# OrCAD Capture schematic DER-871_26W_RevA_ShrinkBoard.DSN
size A3; title: DER-871 26W; rev: A; note: NA
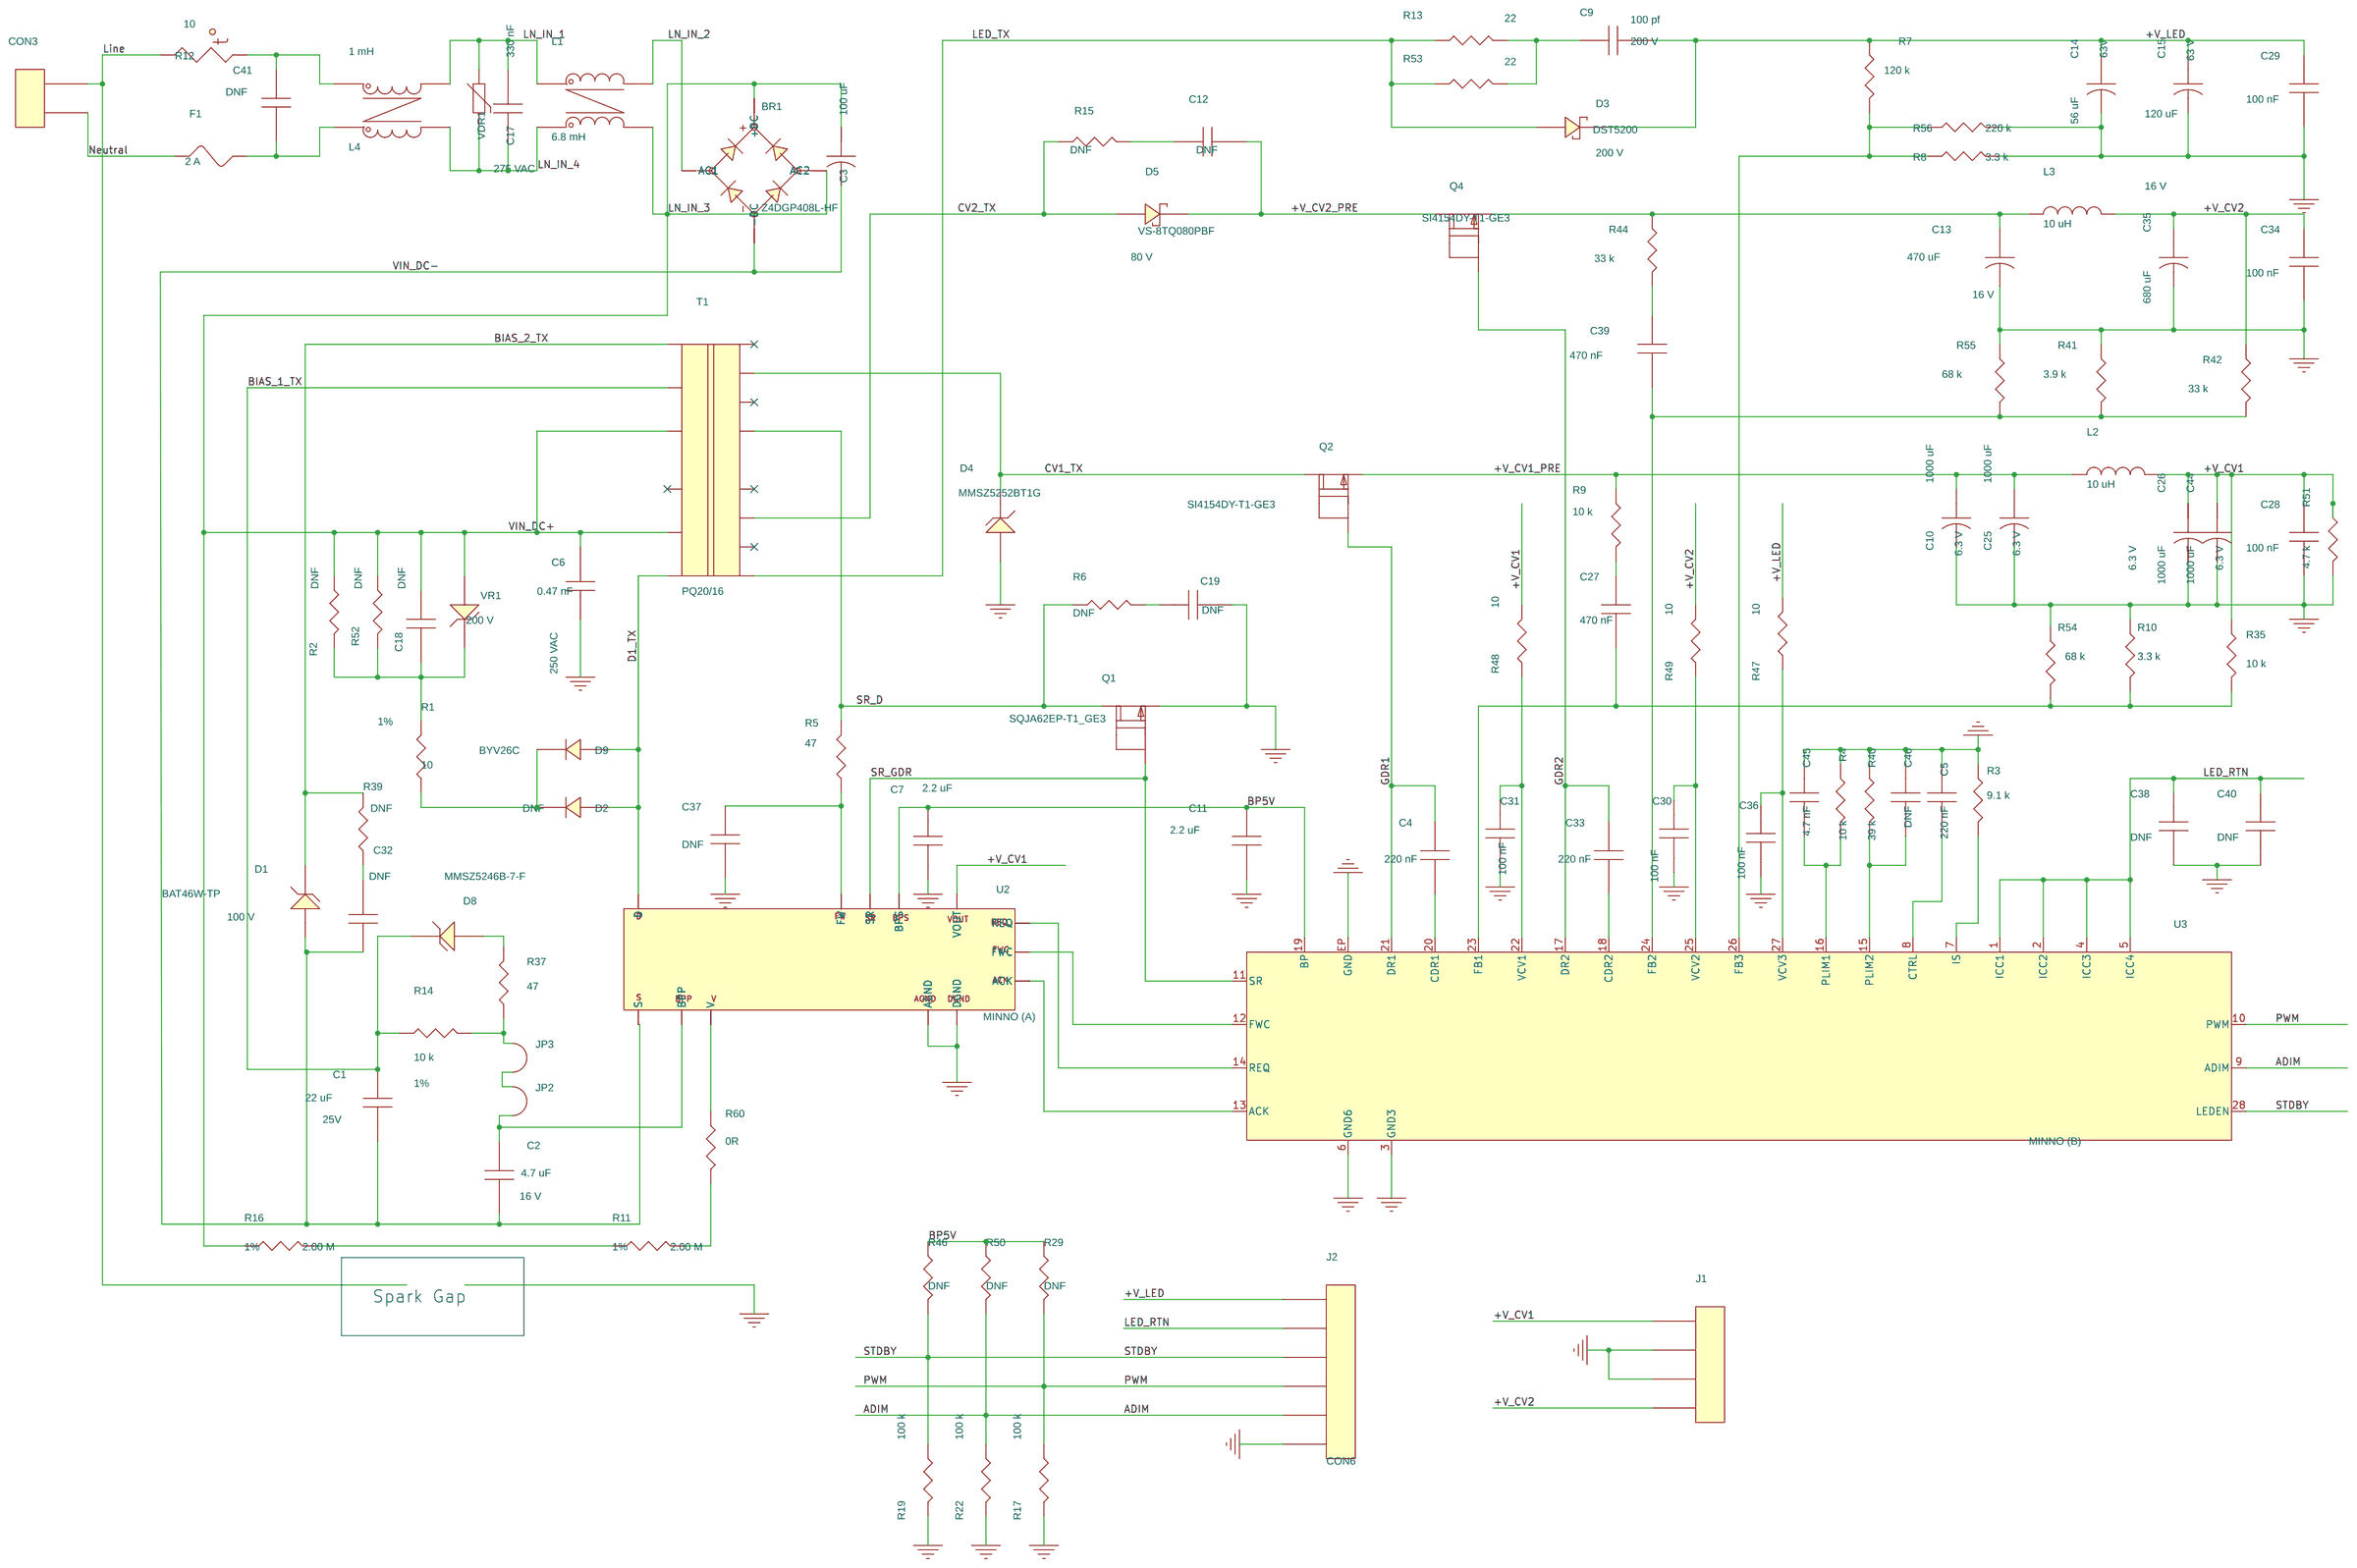
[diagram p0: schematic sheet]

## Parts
BR1  Z4DGP408L-HF  [pi_sm_d_z4d]
C1  22 uF  [pismc1206]
C2  4.7 uF  [pismc0805]
C3  100 uF  [pipolcapclyd630ls300040]
C4  220 nF  [pismc0805]
C5  220 nF  [pismc0805]
C6  0.47 nF  [pinpycaprad540x290ls400040]
C7  2.2 uF  [pismc1206]
C9  100 pf  [pismc0805]
C10  1000 uF  [pipolcapclyd320ls140030]
C11  2.2 uF  [pismc0805]
C12  DNF  [pismc0805]
C13  470 uF  [pipolcapclyd320ls140030]
C14  56 uF  [pipolcapcyld10D14H5LS030]
C15  120 uF  [pipolcapclyd320ls140030]
C17  330 nF  [pinpcaprad760x380590050]
C18  DNF  [pismc1206]
C19  DNF  [pismc0805]
C25  1000 uF  [pipolcapclyd320ls140030]
C26  1000 uF  [pipolcapclyd320ls140030]
C27  470 nF  [pismc0805]
C28  100 nF  [pismc1206]
C29  100 nF  [pismc1206]
C30  100 nF  [pismc0805]
C31  100 nF  [pismc0805]
C32  DNF  [pismc0805]
C33  220 nF  [pismc0805]
C34  100 nF  [pismc1206]
C35  680 uF  [pipolcapclyd320ls140030]
C36  100 nF  [pismc1206]
C37  DNF  [pismc0805]
C38  DNF  [pismc0805]
C39  470 nF  [pismc0805]
C40  DNF  [pismc0805]
C41  DNF  [pinpxcaprad610x260492040]
C44  1000 uF  [pipolcapclyd320ls140030]
C45  4.7 nF  [pismc1206]
C46  DNF  [pismc1206]
CON3  TERMINAL BLOCK  [pi_term_block_2pin]
D1  BAT46W-TP  [pi_sm_sod-123_12]
D2  DNF  [pismdo214ac12]
D3  DST5200  [pidvt0220acreva]
D4  MMSZ5252BT1G  [pi_sm_sod-123_12]
D5  VS-8TQ080PBF  [pidvt0220acreva]
D8  MMSZ5246B-7-F  [pi_sm_sod-123_12]
D9  BYV26C  [pidv200x150x040sod57r]
F1  2 A  [pi_tr5_submin_fuse]
J1  CON4  [pi_Hirose_2p5_4pos]
J2  CON6  [pihdr6pindf125mm]
JP2  J  [pi_jumper200]
JP3  J  [pi_jumper200]
L1  6.8 mH  [piind4p_21x15mmd040]
L2  10 uH  [pi_choke_H625xD539ls290d046]
L3  10 uH  [pi_choke_H625xD539ls290d046]
L4  1 mH  [piind4pKEMET_SC-GS]
Q1  SQJA62EP-T1_GE3  [pismpqfn5x6b]
Q2  SI4154DY-T1-GE3  [PI_SM_SOT669]
Q4  SI4154DY-T1-GE3  [PI_SM_SOT669]
R1  10  [pismr1206]
R2  DNF  [pismr1206]
R3  9.1 k  [pismr0805]
R4  10 k  [pismr1206]
R5  47  [pismr0805]
R6  DNF  [pismr0805]
R7  120 k  [pismr0805]
R8  3.3 k  [pismr0805]
R9  10 k  [pismr0805]
R10  3.3 k  [pismr0805]
R11  2.00 M  [pismr1206]
R12  10  [pirad400x175ls250031]
R13  22  [pismr0805]
R14  10 k  [pismr0805]
R15  DNF  [pismr0805]
R16  2.00 M  [pismr1206]
R17  100 k  [pismr0805]
R19  100 k  [pismr0805]
R22  100 k  [pismr0805]
R29  DNF  [pismr0805]
R35  10 k  [pismr0805]
R37  47  [pismr0805]
R39  DNF  [pismr0805]
R40  39 k  [pismr1206]
R41  3.9 k  [pismr0805]
R42  33 k  [pismr0805]
R44  33 k  [pismr0805]
R46  DNF  [pismr0805]
R47  10  [pismr0805]
R48  10  [pismr0805]
R49  10  [pismr0805]
R50  DNF  [pismr1206]
R51  4.7 k  [pismr0805]
R52  DNF  [pismr1206]
R53  22  [pismr0805]
R54  68 k  [pismr0805]
R55  68 k  [pismr0805]
R56  220 k  [pismr0805]
R60  0R  [pi14wresd100ls500d030]
T1  PQ20/16  [pi_bobbin_pq2016_v_14p_8x6a]
U2  MINNO (A)  [pi_ic_insop_24d]
U3  MINNO (B)  [QFN50P500X500X80-29N]
VDR1  275 Vac  [pidisc500x225ls335x140040]
VR1  SMBJ150A  [pismdo214aa12]

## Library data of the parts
BR1 = DISCRETE_BRIDGE_+~~-: Part Number: 15-01113-00
C1 = CAP_NP: Disp_Voltage: 25V; Part Number: 20-08945-00; Voltage: 25 V
C2 = CAP_NP: Disp_Voltage: 16 V; Part Number: 20-08947-00; Voltage: 16 V
C3 = CAP_POL: ALT_SYMBOLS: pipolcapd630ls3000401600lhoriz; Disp_Voltage: 400 V; FPLIST: pipolcapclyd630ls300040,pipolcapd630ls3000401600lhoriz; Part Number: 20-00491-00; Voltage: 400 V
C4 C33 = CAP_NP: Disp_Voltage: 25 V; Part Number: 20-00237-00; Voltage: 25 V
C5 C30 C31 = CAP_NP: Disp_Voltage: 50 V; Part Number: 20-00904-00; Voltage: 50 V
C6 = CAP_NP: ALT_SYMBOLS: pinpycaprad540x290ls400040h,pinpycaprad500x220ls400040; Disp_Voltage: 250 VAC; FPLIST: pinpycaprad540x290ls400040,pinpycaprad540x290ls400040h,pinpycaprad500x220ls400040; Part Number: 20-00375-00; Voltage: 250 VAC
C7 = CAP_NP: Disp_Voltage: 50 V; Part Number: 20-09241-00; Voltage: 50 V
C9 = CAP_NP: Disp_Voltage: 200 V; Part Number: 24-00030-00; Voltage: 100 V
C10 C25 C44 = CAP_POL: Disp_Voltage: 6.3 V; Part Number: 20-09113-00; Voltage: 6.3 V
C11 = CAP_NP: Disp_Voltage: 10 V; Part Number: 20-08747-00; Voltage: 10 V
C12 = CAP_NP: Disp_Voltage: 100 V; Part Number: 24-00030-00; Voltage: 100 V
C13 = CAP_POL: ALT_SYMBOLS: pipolcapclyd320ls140030430h; Disp_Voltage: 16 V; FPLIST: pipolcapclyd320ls140030,pipolcapclyd320ls140030430h; Part Number: 20-08681-00; Voltage: 16 V
C14 = CAP_POL: ALT_SYMBOLS: pipolcapcyld10D14H5LS030H; Disp_Voltage: 63V; FPLIST: pipolcapcyld10D14H5LS030,pipolcapcyld10D14H5LS030H; Part Number: 20-09126-00; Voltage: 16 V
C15 = CAP_POL: ALT_SYMBOLS: pipolcapclyd8X21P5X3P5LS30h; Disp_Voltage: 63 V; FPLIST: pipolcapclyd320ls140030,pipolcapclyd8X21P5X3P5LS30h; Part Number: 20-09127-00; Voltage: 63 V
C17 = CAP_NP: Disp_Voltage: 275 VAC; Part Number: 20-00542-00; Voltage: 275 VAC
C18 = CAP_NP: Disp_Voltage: 630 V; Part Number: 20-08609-00; Voltage: 630 V
C19 = CAP_NP: ALT_SYMBOLS: pismc0805_1; Disp_Voltage: 200 V; FPLIST: pismc0805,pismc0805_1; Part Number: 20-00737-00; Voltage: 200 V
C26 = CAP_POL: ALT_SYMBOLS: pipolcapclyd320ls140030430h; Disp_Voltage: 6.3 V; FPLIST: pipolcapclyd320ls140030,pipolcapclyd320ls140030430h; Part Number: 20-00417-00; Voltage: 6.3 V
C27 C39 = CAP_NP: Disp_Voltage: 50 V; Part Number: 20-00896-00; Voltage: 50 V
C28 C29 C34 = CAP_NP: Disp_Voltage: 200 V; Part Number: 20-00924-00; Voltage: 200 V
C32 = CAP_NP: Disp_Voltage: 200 V; Part Number: 20-00760-00; Voltage: 200 V
C35 = CAP_POL: ALT_SYMBOLS: pipolcapclyd320ls140d30h750; Disp_Voltage: 16 V; FPLIST: pipolcapclyd320ls140030,pipolcapclyd320ls140d30h750; Part Number: 20-00016-00; Voltage: 16 V
C36 = CAP_NP: Disp_Voltage: 200 V; Part Number: 20-00918-00; Voltage: 200 V
C37 = CAP_NP: Disp_Voltage: 200 V; Part Number: 24-00025-00; Voltage: 200 V
C38 C40 = CAP_NP: Disp_Voltage: 100 V; Part Number: 24-00026-00; Voltage: 100 V
C41 = CAP_NP: Disp_Voltage: 275 VAC; Part Number: 20-00384-00; Voltage: 275 VAC
C45 C46 = CAP_NP: Disp_Voltage: 50 V; Part Number: 20-00175-00; Voltage: 50 V
CON3 = CON2: Part Number: 35-00193-00
D1 = DIODE_ZENER: Disp_Voltage: 100 V; Part Number: 15-01049-00
D2 = DIODE: Part Number: 15-01076-00
D3 = DIODE_SCHOTTKY: Disp_Voltage: 200 V; Part Number: 15-01287-00
D4 = DIODE_ZENER: Part Number: 15-01099-00
D5 = DIODE_SCHOTTKY: Disp_Voltage: 80 V; Part Number: 15-01288-00
D8 = DIODE_ZENER: Part Number: 15-01092-00
D9 = DIODE: ALT_SYMBOLS: pidax425x150040sod57,pidv200x150x040sod57r; FPLIST: pidv200x150x040sod57,pidax425x150040sod57,pidv200x150x040sod57r; Part Number: 15-00128-00
F1 = FUSE: Part Number: 40-00002-00
J1 = CON4: Part Number: 35-00439-00
J2 = CON6: Part Number: 35-00031-00
JP2 JP3 = JUMPER_1: Part Number: 65-00200-00
L1 = CMC__4P_14_23: Part Number: 30-00484-00
L2 L3 = INDUCTOR: Part Number: 30-00460-00
L4 = CMC__4P_12_43: Part Number: 30-00480-00
Q1 = FET_N_SGD_123_4_5678: Part Number: 50-00273-00
Q2 Q4 = FET_N_SGD_123_4_5: ALT_SYMBOLS: pismso8; FPLIST: PI_SM_SOT669,pismso8; Part Number: 50-00257-00
R1 = R: Disp_Tol: 1%; Part Number: 05-00001-00
R2 R52 = R: Disp_Tol: 1%; Part Number: 05-00413-00
R3 = R: Disp_Tol: 1%; Part Number: 05-03381-00
R4 R40 = R: Part Number: 05-01390-00
R5 R37 = R: Disp_Tol: 1%; Part Number: 05-03476-00
R6 = R: Part Number: 05-01477-00
R7 = R: Part Number: 05-01569-00
R8 R10 R41 R54-R56 = R: Disp_Tol: 1%; Part Number: 05-03357-00
R9 R14 R35 = R: Disp_Tol: 1%; Part Number: 05-00684-00
R11 R16 = R: Disp_Tol: 1%; Part Number: 05-03156-00
R12 = THERMISTOR: ALT_SYMBOLS: pirad400x175ls250040_h; FPLIST: pirad400x175ls250031,pirad400x175ls250040_h; Part Number: 90-00013-00
R13 R15 R39 R47-R49 R53 = R: Disp_Tol: 1%; Part Number: 05-00492-00
R17 R19 R22 R29 R46 = R: Part Number: 05-01567-00
R42 R44 = R: Disp_Tol: 1%; Part Number: 05-00729-00
R50 = R: Part Number: 05-01400-00
R51 = R: Disp_Tol: 1%; Part Number: 05-03373-00
R60 = R: ALT_SYMBOLS: pi14wvresd100ls125d030,pi14wvresd100ls150d030,pi14wvresd100ls200d030,pi14wvresd100ls300d030,pi14wresd100ls400d030,pi14wresd100ls500d030; Disp_Tol: 1%; FPLIST: pi14wvresd100ls100d030,pi14wvresd100ls125d030,pi14wvresd100ls150d030,pi14wvresd100ls200d030,pi14wvresd100ls300d030,pi14wresd100ls400d030,pi14wresd100ls500d030; Part Number: 05-01784-00
T1 = BPQ2016_14P_6-8-GENERIC: Part Number: 25-01174-00
U2 = MinnoPriSec: FPLIST: pi_ic_insop_24b,pi_ic_insop_24d; Part Number: 10-01060-00
U3 = MINNO_Master_QFN_RevB: ALT_SYMBOLS: QFN50P500X500X80-29NTH2; FPLIST: QFN50P500X500X80-29N,QFN50P500X500X80-29NTH2; Part Number: 10-01061-01
VDR1 = VARISTOR: Part Number: 85-00014-00
VR1 = DIODE_ZENER: Disp_Voltage: 200 V; Part Number: 15-00427-00

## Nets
GND POWER: C5.1 C6.1 C7.2 C10.2 C11.2 C13.2 C14.2 C15.2 C19.2 C25.2 C26.2 C28.2 C29.2 C30.2 C31.2 C34.2 C35.2 C36.2 C37.2 C38.2 C40.2 C44.2 C45.1 C46.1 D4.2 J1.2 J1.3 J2.6 Q1.1(S) R3.1 R4.1 R8.2 R10.1 R17.2 R19.2 R22.2 R40.1 R41.1 R51.2 R54.1 R55.1 R56.2 U2.2(DGND) U2.3(AGND) U3.3(GND3) U3.6(GND6) U3.EP(GND)
VIN_DC+: BR1.1(+DC) C3.1 C6.2 C18.1 R2.1 R16.1 R52.1 T1.3 T1.5 VR1.2
VIN_DC-: BR1.4(-DC) C1.2 C2.2 C3.2 C32.1 D1.2 U2.16(S)
+V_CV1: C26.1 C28.1 C44.1 J1.1 L2.2 R35.1 R48.2 R51.1 U2.8(VOUT)
+V_CV1_PRE: C10.1 C25.1 L2.1 Q2.1(S) R9.1
+V_CV2: C34.1 C35.1 J1.4 L3.2 R42.1 R49.2
+V_CV2_PRE: C12.2 D5.1 Q4.5(D)
+V_LED: C9.2 C14.1 C15.1 C29.1 D3.1 J2.1 R7.1 R47.2
ADIM: J2.5 R22.1 R50.2 U3.9(ADIM)
BIAS_1_TX: C1.1 D8.1 R14.1 T1.2
BIAS_2_TX: D1.1 R39.2 T1.1
BP5V: C7.1 C11.1 R29.1 R46.1 R50.1 U2.6(BPS) U3.19(BP)
CV1_TX: D4.1 Q2.5(D) T1.13
CV2_TX: D5.2 R15.1 T1.9
D1_TX: D2.2 D9.2 T1.6 U2.24(D)
GDR1: C4.1 Q2.4(G) U3.21(DR1)
GDR2: C33.1 Q4.4(G) U3.17(DR2)
LED_RTN: C38.1 C40.1 J2.2 U3.1(ICC1) U3.2(ICC2) U3.4(ICC3) U3.5(ICC4)
LED_TX: D3.2 R13.1 R53.1 T1.7
Line: CON3.2 R12.1
LN_IN_1: C17.2 L1.2 L4.2 VDR1.1
LN_IN_2: BR1.2(AC1) L1.3
LN_IN_3: BR1.3(AC2) L1.4
LN_IN_4: C17.1 L1.1 L4.3 VDR1.2
Neutral: CON3.1 F1.1
PWM: J2.4 R17.1 R29.2 U3.10(PWM)
SR_D: Q1.5(D) R5.1 R6.1 T1.11
SR_GDR: Q1.4(G) U2.7(SR) U3.11(SR)
STDBY: J2.3 R19.1 R46.2 U3.28(LEDEN)
N265348: C18.2 R1.2 R2.2 R52.2 VR1.1
N265875: JP3.1 R14.2 R37.1
N265882: D8.2 R37.2
N266437: C2.1 JP2.2 U2.14(BPP)
N266812: R60.1 U2.13(V)
N268540: U2.4(ACK) U3.13(ACK)
N269745: R7.2 R8.1 R56.1 U3.26(FB3)
N276717: C4.2 U3.20(CDR1)
N282159: C12.1 R15.2
N282590: C37.1 R5.2 U2.9(FW)
N291571: U2.5(FWC) U3.12(FWC)
N348677: D2.1 D9.1 R1.1
N383807: C27.2 R10.2 R35.2 R54.2 U3.23(FB1)
N496691: C32.2 R39.1
N515201: C13.1 L3.1 Q4.1(S) R44.1
N529887: U2.1(REQ) U3.14(REQ)
N563406: C9.1 R13.2 R53.2
N641623: R11.1 R16.2
N641634: R11.2 R60.2
N670571: C39.2 R41.2 R42.2 R55.2 U3.24(FB2)
N670621: C27.1 R9.2
N670685: C39.1 R44.2
N707266: C41.2 F1.2 L4.4
N707302: C41.1 L4.1 R12.2
N797298: C19.1 R6.2
N16752139: C45.2 R4.2 U3.16(PLIM1)
N16752147: C46.2 R40.2 U3.15(PLIM2)
N16752545: C31.1 R48.1 U3.22(VCV1)
N16752942: C33.2 U3.18(CDR2)
N16753892: C30.1 R49.1 U3.25(VCV2)
N16755678: C36.1 R47.1 U3.27(VCV3)
N16756663: R3.2 U3.7(IS)
N16756996: C5.2 U3.8(CTRL)
N16782134: JP2.1 JP3.2

Not connected (* = marked no-connect by the designer): Q1 2(S2) 3(S3) 6(D6) 7(D7) 8(D8); Q2 2(S2) 3(S3); Q4 2(S2) 3(S3); T1 4* 8* 10* 12* 14*

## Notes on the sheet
- Spark Gap
